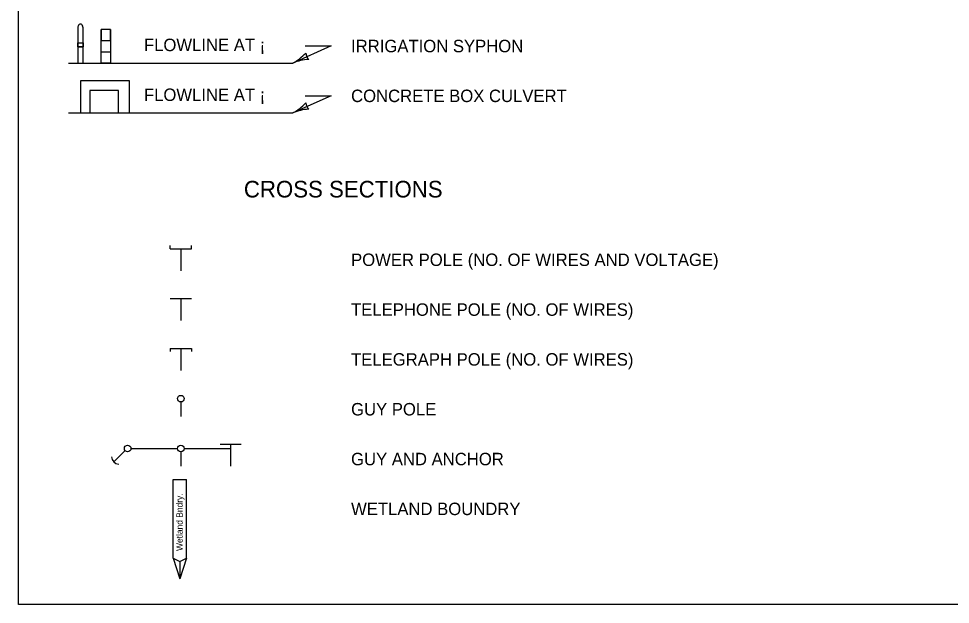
# Model space of a CAD drawing. Extents: x 49991.4 to 50021, y 49987.6 to 50011.4.
# Drawn here: x 49999.384 to 50003.87, y 49987.799 to 49990.62 of the extents above; entities that cross this region are included whole.
import ezdxf

# ---------------------------------------------------------------- set-up
doc = ezdxf.new("R2010")
doc.units = 0
for name, color, linetype in [('Level 1', 7, 'Continuous'), ('Level 2', 7, 'Continuous'), ('Level 3', 7, 'Continuous')]:
    doc.layers.add(name, color=color, linetype=linetype)

msp = doc.modelspace()

# ---------------------------------------------------------------- linework, layer by layer
at = {"layer": 'Level 1'}
for p, q in [((49999.6683, 49990.5752), (49999.6683, 49990.5752)), ((49999.6683, 49990.5752), (49999.6683, 49990.5632)), ((49999.6683, 49990.5632), (49999.6683, 49990.5032)), ((49999.6683, 49990.5632), (49999.6683, 49990.5032)), ((49999.6683, 49990.5632), (49999.6683, 49990.5032)), ((49999.6938, 49990.5632), (49999.6938, 49990.5752)), ((49999.6938, 49990.5032), (49999.6938, 49990.5632)), ((49999.78, 49990.5684), (49999.78, 49990.4064)), ((49999.7806, 49990.5685), (49999.7806, 49990.5145)), ((49999.8256, 49990.5685), (49999.7806, 49990.5685)), ((49999.8256, 49990.5145), (49999.8256, 49990.5685)), ((49999.8256, 49990.5685), (49999.8256, 49990.4065)), ((49999.6683, 49990.5032), (49999.6938, 49990.5032)), ((49999.6683, 49990.5032), (49999.6938, 49990.5032)), ((49999.6683, 49990.4852), (49999.6683, 49990.5032)), ((49999.6683, 49990.5032), (49999.6683, 49990.4852)), ((49999.6938, 49990.5032), (49999.6938, 49990.4852)), ((49999.6938, 49990.4852), (49999.6938, 49990.5032)), ((49999.7806, 49990.5145), (49999.8256, 49990.5145)), ((49999.6683, 49990.4852), (49999.6938, 49990.4852)), ((49999.6938, 49990.4852), (49999.6683, 49990.4852)), ((49999.6938, 49990.4852), (49999.6683, 49990.4852)), ((49999.6683, 49990.4852), (49999.6683, 49990.4061)), ((49999.6938, 49990.4061), (49999.6938, 49990.4852)), ((49999.7806, 49990.4065), (49999.7806, 49990.4605)), ((49999.7806, 49990.4605), (49999.8256, 49990.4605)), ((49999.8256, 49990.4605), (49999.8256, 49990.4065)), ((49999.6243, 49990.4062), (50000.7043, 49990.4062)), ((49999.6683, 49990.4061), (49999.6938, 49990.4061)), ((49999.8256, 49990.4065), (49999.7806, 49990.4065)), ((49999.9174, 49990.321), (49999.681, 49990.321)), ((49999.681, 49990.321), (49999.681, 49990.1662)), ((49999.9174, 49990.1662), (49999.9174, 49990.321)), ((49999.864, 49990.2739), (49999.7256, 49990.2739)), ((49999.7256, 49990.2739), (49999.7256, 49990.1662)), ((49999.864, 49990.1662), (49999.864, 49990.2739)), ((49999.6243, 49990.1662), (50000.7043, 49990.1662)), ((49999.681, 49990.1662), (49999.9174, 49990.1662)), ((49999.7256, 49990.1662), (49999.864, 49990.1662)), ((50000.1133, 49989.5118), (50000.1133, 49989.5268)), ((50000.1133, 49989.5118), (50000.2153, 49989.5118)), ((50000.1643, 49989.5118), (50000.1643, 49989.4058)), ((50000.2153, 49989.5118), (50000.2153, 49989.5268)), ((50000.1133, 49989.2718), (50000.2153, 49989.2718)), ((50000.1643, 49989.2718), (50000.1643, 49989.1658)), ((50000.1133, 49989.0318), (50000.2153, 49989.0318)), ((50000.1133, 49989.0318), (50000.1133, 49989.0168)), ((50000.1643, 49989.0318), (50000.1643, 49988.9258)), ((50000.2153, 49989.0318), (50000.2153, 49989.0168)), ((50000.1643, 49988.7738), (50000.1643, 49988.7038)), ((50000.3533, 49988.5698), (50000.4553, 49988.5698)), ((50000.4043, 49988.5698), (50000.4043, 49988.4638)), ((49999.8412, 49988.4848), (49999.8962, 49988.5398)), ((49999.9243, 49988.5497), (50000.1484, 49988.5497)), ((50000.1643, 49988.5338), (50000.1643, 49988.4638)), ((50000.1803, 49988.5497), (50000.4043, 49988.5497)), ((50000.128, 49988.0218), (50000.128, 49988.4002)), ((50000.128, 49988.4002), (50000.1917, 49988.4002)), ((50000.1917, 49988.0218), (50000.1917, 49988.4002)), ((50000.128, 49988.0218), (50000.1599, 49987.9212)), ((50000.128, 49988.0218), (50000.1597, 49988.0055)), ((50000.1597, 49988.0055), (50000.1917, 49988.0218)), ((50000.1917, 49988.0218), (50000.1599, 49987.9212)), ((50000.1599, 49988.0056), (50000.1599, 49987.9212))]:
    msp.add_line(p, q, dxfattribs=at)
msp.add_lwpolyline([(49999.3835, 49998.9992), (50016.7501, 49998.9992), (50016.7501, 49987.7988), (49999.3835, 49987.7988)], close=True, dxfattribs=at)
for centre in [(50000.1643, 49988.7898), (49999.9084, 49988.5498), (50000.1643, 49988.5498)]:
    msp.add_circle(centre, 0.0159, dxfattribs=at)
msp.add_arc((49999.8656, 49988.5093), 0.0346, 180, 270, dxfattribs=at)
msp.add_ellipse((49999.6811, 49990.5752), major_axis=(0, 0.0185), ratio=0.68738, start_param=4.712389, end_param=7.853982, dxfattribs=at)
at = {"layer": 'Level 3'}
for p, q in [((50000.8877, 49990.489), (50000.7043, 49990.4063)), ((50000.7633, 49990.489), (50000.8877, 49990.489)), ((50000.8877, 49990.2489), (50000.7043, 49990.1662)), ((50000.7633, 49990.2489), (50000.8877, 49990.2489))]:
    msp.add_line(p, q, dxfattribs=at)
for centre, radius, start, end in [((50000.5938, 49990.6115), 0.233, 298.3072, 317.557), ((50000.82, 49990.4615), 0.0548, 187.6187, 223.341), ((50000.7916, 49990.2019), 0.2223, 92.9359, 113.1194), ((50000.5938, 49990.3714), 0.233, 298.3072, 317.557), ((50000.7916, 49989.9618), 0.2223, 92.9359, 113.1194), ((50000.82, 49990.2214), 0.0548, 187.6187, 223.341)]:
    msp.add_arc(centre, radius, start, end, dxfattribs=at)

# ---------------------------------------------------------------- texts
at = {"layer": 'Level 1'}
msp.add_text('Wetland Bndry.', height=0.030322, rotation=90, dxfattribs=at).set_placement((50000.1732, 49988.0561))
at = {"layer": 'Level 2'}
for s, height, p in [('FLOWLINE AT ¡', 0.06, (49999.987, 49990.4637)), ('IRRIGATION SYPHON   ', 0.059999, (50000.9843, 49990.4583)), ('FLOWLINE AT ¡', 0.06, (49999.987, 49990.2236)), ('CONCRETE BOX CULVERT', 0.059999, (50000.9843, 49990.2183)), ('CROSS SECTIONS', 0.08, (50000.4681, 49989.7588)), ('POWER POLE (NO. OF WIRES AND VOLTAGE)   ', 0.059999, (50000.9843, 49989.4288)), ('TELEPHONE POLE (NO. OF WIRES)           ', 0.059999, (50000.9843, 49989.1888)), ('TELEGRAPH POLE (NO. OF WIRES)           ', 0.059999, (50000.9843, 49988.9488)), ('GUY POLE            ', 0.059999, (50000.9843, 49988.7088)), ('GUY AND ANCHOR      ', 0.059999, (50000.9843, 49988.4688)), ('WETLAND BOUNDRY      ', 0.059999, (50000.9843, 49988.2288))]:
    msp.add_text(s, height=height, dxfattribs=at).set_placement(p)

doc.saveas('drawing.dxf')
